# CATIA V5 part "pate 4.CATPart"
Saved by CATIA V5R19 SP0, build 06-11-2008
Part number: Part4
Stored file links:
  F:\554\pate 4.CATPart
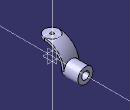
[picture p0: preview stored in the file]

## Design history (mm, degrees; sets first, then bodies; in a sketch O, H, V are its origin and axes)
Body1 (main body)
  Sketch1 on yz-plane, origin (0, 0, 0), H (0, 1, 0), V (0, 0, 1)
    arc A1 centre (0, 0) radius 55 from (55, 0) to (0, 55) ccw
    point P1 (55, 0)
    point P2 (0, 55)
    line L1 (55, 0) -> (0, 0)
    line L2 (0, 0) -> (0, 55)
    radius A1 = 55
    coincidence: P1 H, P2 V
    horizontal: L1 H
    vertical: L2 V
  Shaft1: profile Sketch1, axis Sketch1.L1, angle 90, second angle 90
  Sketch2 on yz-plane, origin (0, 0, 0), H (0, 1, 0), V (0, 0, 1)
    line L1 (0, 0) -> (87.8479, 0)
    line L2 (87.8479, 0) -> (87.8479, -20)
    line L3 (87.8479, -20) -> (0, -20)
    line L4 (0, -20) -> (0, 0)
    length L2 = 20
    horizontal: L1 H, L3 H
    vertical: L2 V, L4 V
  Shaft2: profile Sketch2, axis Sketch2.L1, angle 0, second angle 360
  Sketch3 on face of Shaft2, origin (0, 0, 0), H (1, 0, 0), V (0, 0, 1)
    line L1 (20, 64.8451) -> (94.7318, 64.8451)
    line L2 (94.7318, 64.8451) -> (94.7318, -19.664)
    line L3 (94.7318, -19.664) -> (20, -19.664)
    line L4 (20, -19.664) -> (20, 64.8451)
    line L5 (-94.7318, 64.8451) -> (-20, 64.8451)
    line L6 (-20, -19.664) -> (-94.7318, -19.664)
    line L7 (-20, 64.8451) -> (-20, -19.664)
    line L8 (-94.7318, -19.664) -> (-94.7318, 64.8451)
    distance L7 L4 = 40
    horizontal: L1 H, L3 H, L5 H, L6 H
    vertical: L2 V, L4 V, L7 V, L8 V
    symmetry: L7 L4 V, L2 L8 V
    coincidence: L1 L5, L3 L6
  Pocket1: profile Sketch3, direction (0, 1, 0), through (limit type 3)
  Sketch4 on face of Pocket1 from Sketch3.L7, origin (-20, 0, 0), H (0, -1, 0), V (0, 0, 1)
    arc A1 centre (0, 0) radius 45 from (0, 45) to (-45, 0) ccw
    point P1 (0, 45)
    point P2 (-45, 0)
    line L1 (0, 45) -> (0, -57.9537)
    line L2 (0, -57.9537) -> (-45, -57.9537)
    line L3 (-45, -57.9537) -> (-45, 0)
    radius A1 = 45
    coincidence: P1 V, P2 H
    vertical: L1 V
    horizontal: L2 H
    tangency: L3 A1
  Pocket2: profile Sketch4, direction (-1, 0, 0), through (limit type 3)
  Plane1: type Angle, Angle 90, Direction edge [face of Pocket2 from Sketch4.A1 | face of Shaft2], RefPlane face of Shaft2
  Sketch5 on Plane1, origin (0, 0, 45), H (1, 0, 0), V (0, -1, 0)
    arc A1 centre (0, 0) radius 20 from (20, 0) to (-20, 0) ccw
    point P1 (-20, 0)
    point P2 (20, 0)
    reference projected point E1 (-20, 0) from vertex [face of Shaft2 | face of Pocket2 from Sketch4.A1 | face of Pocket1 from Sketch3.L7]
    line L1 (-20, 0) -> (20, 0)
    coincidence: P1 H, P2 H, P1 E1
    horizontal: L1 H
  Pad1: profile Sketch5, direction (0, 0, 1), length 6.8
  Sketch6 on face of Pocket1 from Sketch3.L7, origin (-20, 0, 0), H (0, -1, 0), V (0, 0, 1)
    line L1 (44.7496, 73.0943) -> (-21.4975, 73.0943)
    line L2 (-21.4975, 73.0943) -> (-21.4975, 51.8)
    line L3 (-21.4975, 51.8) -> (44.7496, 51.8)
    line L4 (44.7496, 51.8) -> (44.7496, 73.0943)
    reference projected line E1 (20, 51.8) -> (0, 51.8) from edge [end face of Pad1 | face of Pad1 from Sketch5.A1]
    horizontal: L1 H, L3 H
    vertical: L2 V, L4 V
    coincidence: L3 E1
  Pocket3: profile Sketch6, direction (-1, 0, 0), through (limit type 3)
  Sketch7 on face of Shaft2 from Sketch2.L2, origin (0, 87.8479, 0), H (-1, 0, 0), V (0, 0, 1)
    circle A1 centre (0, 0) radius 10
    radius A1 = 10
  Pocket4: profile Sketch7, direction (0, -1, 0), through (limit type 3)
  Sketch8 on face of Pocket3, origin (0, 0, 51.8), H (1, 0, 0), V (0, 1, 0)
    circle A1 centre (0, 0) radius 5
    radius A1 = 5
  Pocket5: profile Sketch8, direction (0, 0, -1), through (limit type 3)
  Point1: type Center, Curve edge [start face of Pad1 | face of Pocket5 from Sketch8.A1]
  Line1: type Normal, RefSkin start face of Pad1, Start 0, End 20, RefPoint Point1
  Point2: type Center, Curve edge [face of Shaft2 from Sketch2.L2 | face of Pocket4 from Sketch7.A1]
  Line2: type Normal, RefSkin face of Shaft2 from Sketch2.L2, Start 0, End 20, RefPoint Point2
